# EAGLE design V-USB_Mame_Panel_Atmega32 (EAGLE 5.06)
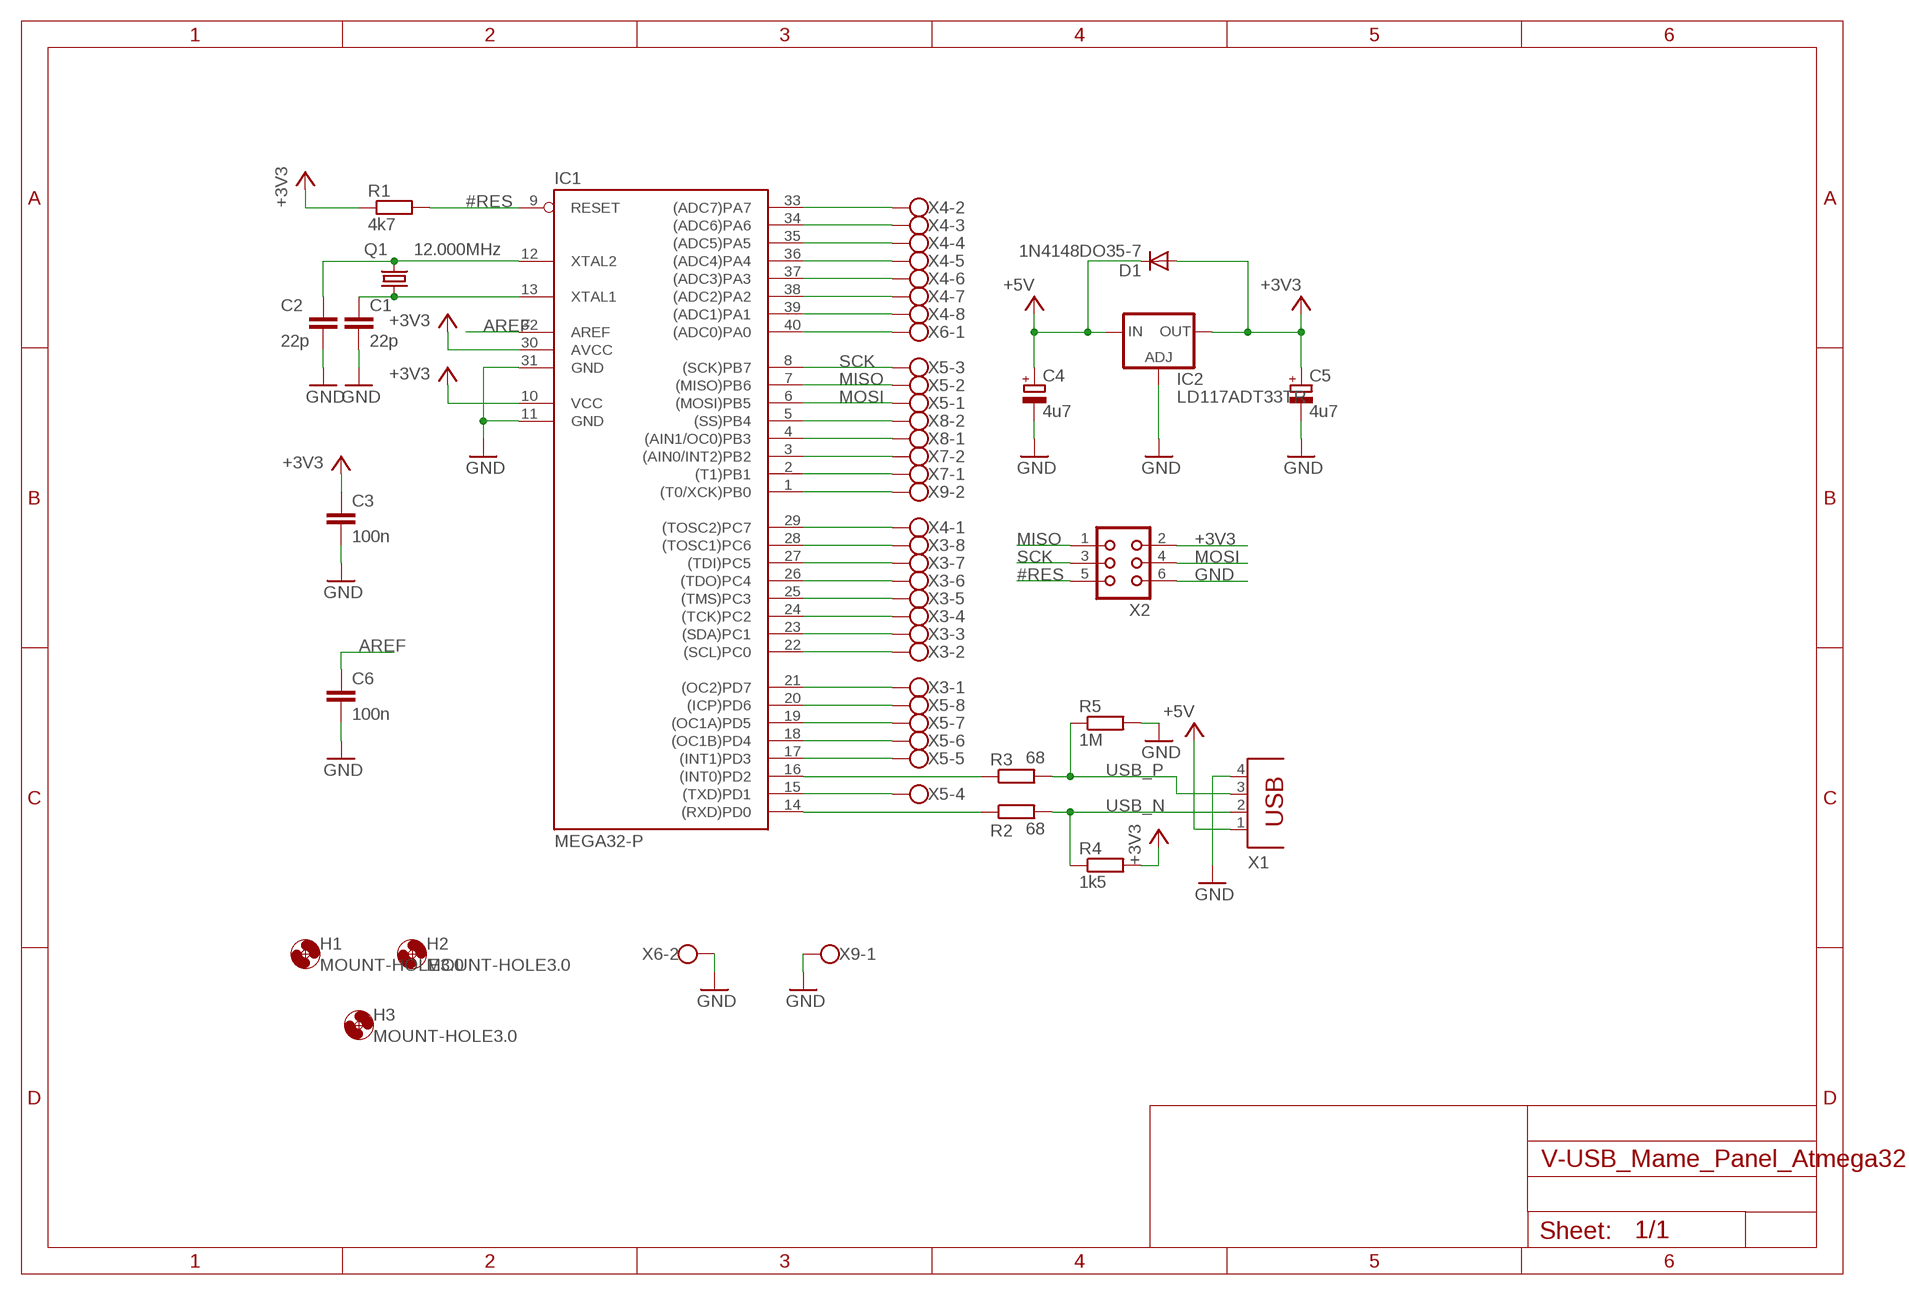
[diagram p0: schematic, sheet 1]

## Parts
C1  22p  C2.5/2  [C2.5-2]
C2  22p  C2.5/2  [C2.5-2]
C3  100n  C5/2.5  [C5B2.5]
C4  4u7  CPOL-EUE2.5-6  [E2,5-6]
C5  4u7  CPOL-EUE2.5-6  [E2,5-6]
C6  100n  C5/2.5  [C5B2.5]
D1  1N4148DO35-7  [DO35-7]
H1  MOUNT-HOLE3.0  [3,0]
H2  MOUNT-HOLE3.0  [3,0]
H3  MOUNT-HOLE3.0  [3,0]
IC1  MEGA32-P  [DIL40]
IC2  LD117ADT33TR  [DPACK]
Q1  12.000MHz  CRYSTALHC18U-V  [HC18U-V]
R1  4k7  R-EU_0207/10  [0207/10]
R2  68  R-EU_0207/10  [0207/10]
R3  68  R-EU_0207/10  [0207/10]
R4  1k5  R-EU_0207/10  [0207/10]
R5  1M  R-EU_0207/10  [0207/10]
X1  PN61729  [PN61729]
X2  CON06L  [CON06L]
X3  W237-08P  [W237-8P]
X4  W237-08P  [W237-8P]
X5  W237-08P  [W237-8P]
X6  W237-02P  [W237-132]
X7  W237-02P  [W237-132]
X8  W237-02P  [W237-132]
X9  W237-02P  [W237-132]

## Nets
#RES: IC1.9(RESET) R1.2 X2.5
+3V3: C3.1 C5.+ D1.A IC1.10(VCC) IC1.30(AVCC) IC2.4(OUT) R1.1 R4.2 X2.2
+5V: C4.+ D1.C IC2.3(IN) X1.1
AREF: C6.1 IC1.32(AREF)
GND: C1.2 C2.2 C3.2 C4.- C5.- C6.2 IC1.11(GND) IC1.31(GND) IC2.1(ADJ) R5.2 X1.4 X2.6 X6.2 X9.1
MISO: IC1.7((MISO)PB6) X2.1 X5.2
MOSI: IC1.6((MOSI)PB5) X2.4 X5.1
N$1: IC1.17((INT1)PD3) X5.5
N$2: IC1.16((INT0)PD2) R3.1
N$3: C1.1 IC1.13(XTAL1) Q1.1
N$4: C2.1 IC1.12(XTAL2) Q1.2
N$5: IC1.14((RXD)PD0) R2.1
N$6: IC1.21((OC2)PD7) X3.1
N$7: IC1.22((SCL)PC0) X3.2
N$9: IC1.2((T1)PB1) X7.1
N$10: IC1.3((AIN0/INT2)PB2) X7.2
N$11: IC1.5((SS)PB4) X8.2
N$12: IC1.4((AIN1/OC0)PB3) X8.1
N$13: IC1.15((TXD)PD1) X5.4
N$14: IC1.18((OC1B)PD4) X5.6
N$15: IC1.19((OC1A)PD5) X5.7
N$16: IC1.20((ICP)PD6) X5.8
N$17: IC1.23((SDA)PC1) X3.3
N$18: IC1.24((TCK)PC2) X3.4
N$19: IC1.25((TMS)PC3) X3.5
N$20: IC1.26((TDO)PC4) X3.6
N$21: IC1.27((TDI)PC5) X3.7
N$22: IC1.28((TOSC1)PC6) X3.8
N$23: IC1.29((TOSC2)PC7) X4.1
N$24: IC1.33((ADC7)PA7) X4.2
N$25: IC1.34((ADC6)PA6) X4.3
N$26: IC1.35((ADC5)PA5) X4.4
N$27: IC1.36((ADC4)PA4) X4.5
N$28: IC1.37((ADC3)PA3) X4.6
N$29: IC1.38((ADC2)PA2) X4.7
N$30: IC1.39((ADC1)PA1) X4.8
N$31: IC1.40((ADC0)PA0) X6.1
N$32: IC1.1((T0/XCK)PB0) X9.2
SCK: IC1.8((SCK)PB7) X2.3 X5.3
USB_N: R2.2 R4.1 X1.2
USB_P: R3.2 R5.1 X1.3

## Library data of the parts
C1-C3 C6 = capacitor-wima:C: CAPACITOR
C4 C5 = resistor:CPOL-EU: POLARIZED CAPACITOR, European symbol
D1 = diode:1N4148: DIODE
H1-H3 = holes:MOUNT-HOLE: MOUNTING HOLE with drill center marker
IC1 = atmel:MEGA32-P: MICROCONTROLLER 32 Kbytes FLASH 2 Kbytes SRAM 1 Kbytes EEPROM USART 8-channel 10 bit ADC Source: www.atmel.com .. doc2503.pdf
IC2 = v-reg:LD117A?*: Low drop fixed and adjustable positive voltage regulators 1 A Source: http://www.st.com/stonline/products/literature/ds/7194/ld1117axx.pdf
Q1 = crystal:CRYSTAL: CRYSTAL
R1-R5 = resistor:R-EU_: RESISTOR, European symbol
X1 = con-berg:PN61729: BERG USB connector
X2 = con-harting:CON06L: CONNECTOR
X3-X5 = con-wago-508:W237-08P: WAGO SREW CLAMP
X6-X9 = con-wago-508:W237-02P: WAGO SREW CLAMP

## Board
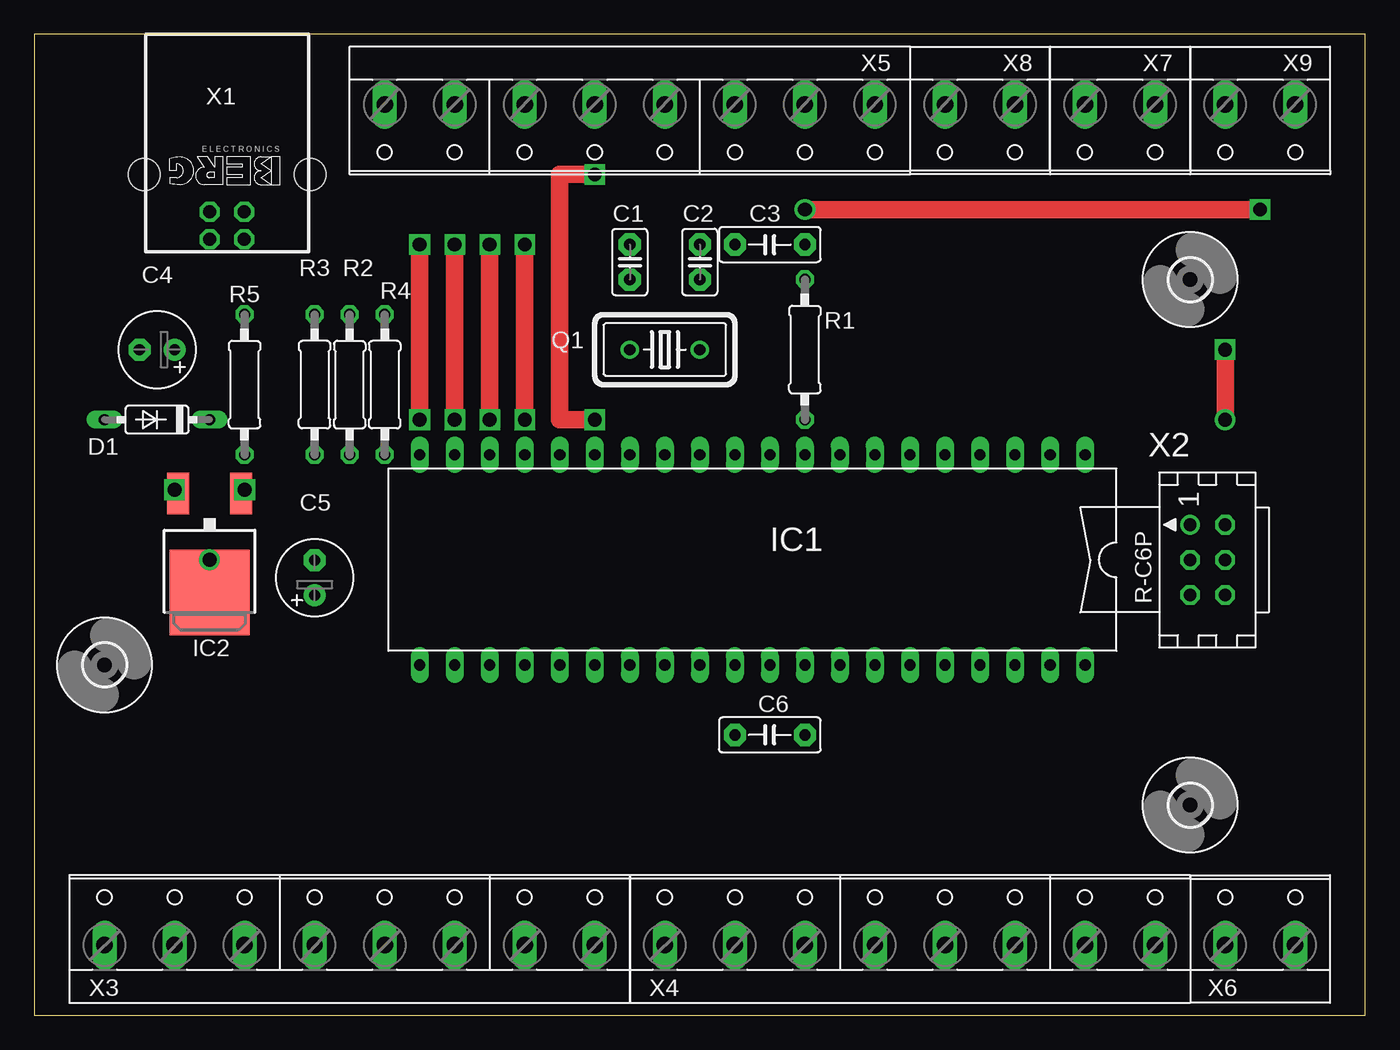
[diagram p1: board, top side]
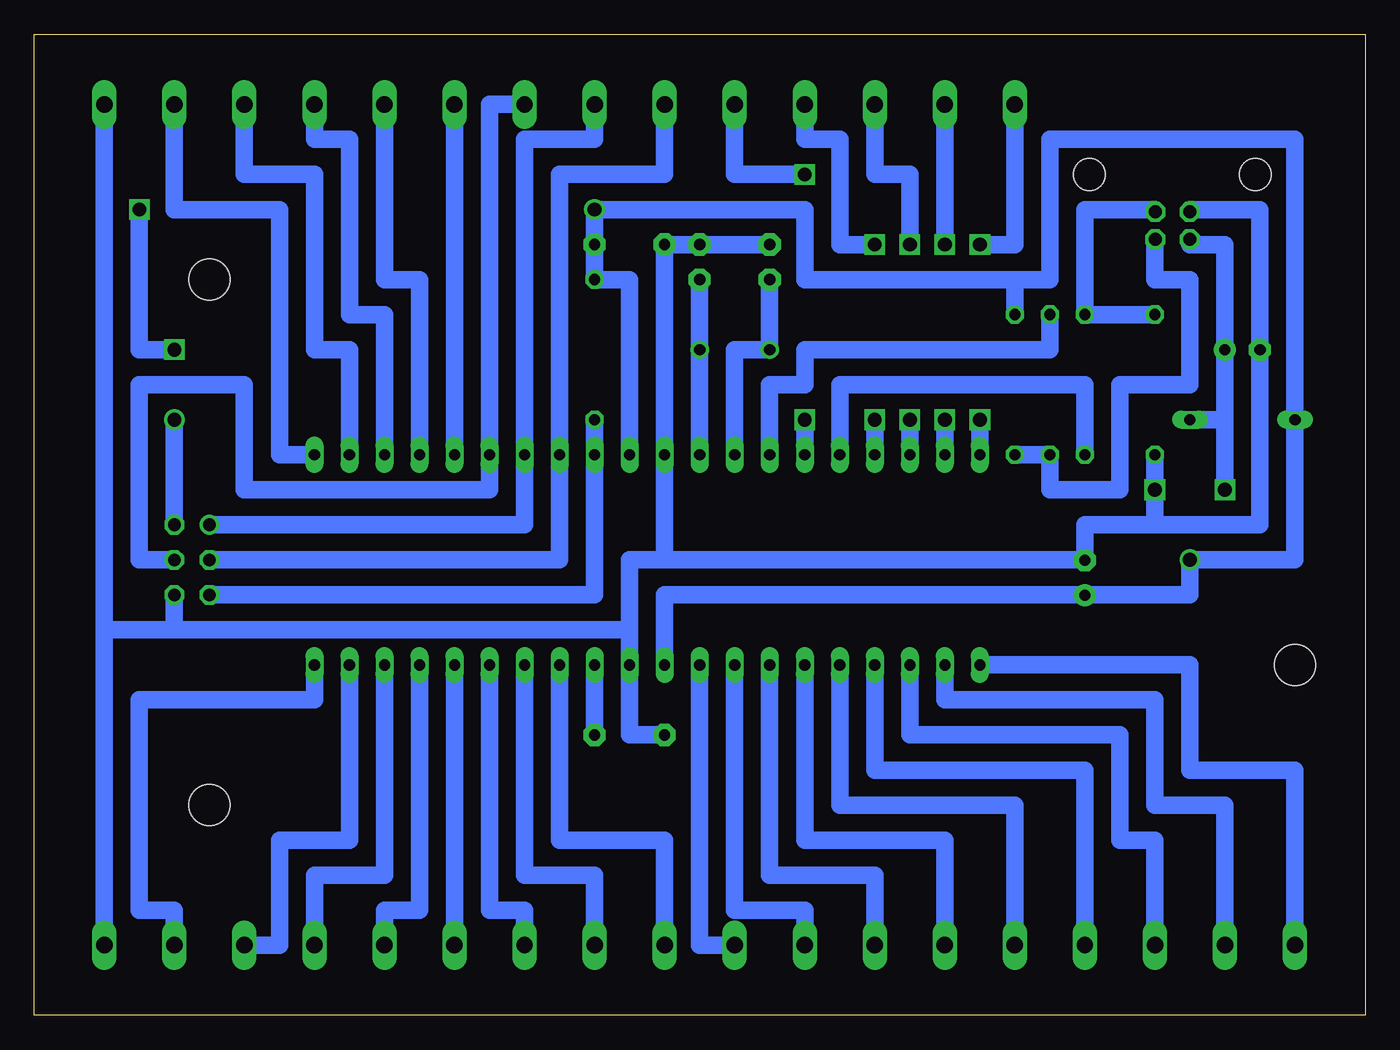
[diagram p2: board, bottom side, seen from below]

Size 96.51 x 71.11 mm. Coordinates in mm from the lower left corner, seen from the top.
Outline: 0,0 96.51,0 96.51,71.11 0,71.11 0,0
Copper layers (1*16): Top 0.035mm / dielectric 1.5mm / Bottom 0.035mm
Design rules "default": minimum track width 10mil, minimum drill 24mil, track to track 8mil, track to pad 8mil, pad to pad 8mil, via to via 8mil, smd to smd 8mil, copper to edge 40mil, drill to drill 8mil, minimum pad ring 10mil, minimum via ring 8mil, stop-mask expansion 4mil, vias tented up to drill 0mil, thermal gap 10mil

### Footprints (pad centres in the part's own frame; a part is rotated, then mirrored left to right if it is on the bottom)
C2.5-2 = drill 0.813 pad 1.6 octagon: 1 -1.27,0; 2 1.27,0
C5B2.5 = drill 0.813 pad 1.6 octagon: 1 -2.54,0; 2 2.54,0
E2,5-6 = drill 0.813 pad 1.6 round: + -1.27,0 | drill 0.813 pad 1.6 octagon: - 1.27,0
DO35-7 = drill 0.813 long: A 3.81,0; C -3.81,0
3,0 = hole 3: 0,0
DIL40 = drill 0.813 long: 1 -24.13,-7.62; 2 -21.59,-7.62; 3 -19.05,-7.62; 4 -16.51,-7.62; 5 -13.97,-7.62; 6 -11.43,-7.62; 7 -8.89,-7.62; 8 -6.35,-7.62; 9 -3.81,-7.62; 10 -1.27,-7.62; 11 1.27,-7.62; 12 3.81,-7.62; 13 6.35,-7.62; 14 8.89,-7.62; 15 11.43,-7.62; 16 13.97,-7.62; 17 16.51,-7.62; 18 19.05,-7.62; 19 21.59,-7.62; 20 24.13,-7.62; 21 24.13,7.62; 22 21.59,7.62; 23 19.05,7.62; 24 16.51,7.62; 25 13.97,7.62; 26 11.43,7.62; 27 8.89,7.62; 28 6.35,7.62; 29 3.81,7.62; 30 1.27,7.62; 31 -1.27,7.62; 32 -3.81,7.62; 33 -6.35,7.62; 34 -8.89,7.62; 35 -11.43,7.62; 36 -13.97,7.62; 37 -16.51,7.62; 38 -19.05,7.62; 39 -21.59,7.62; 40 -24.13,7.62
DPACK = smd 1.6 x 3: 1 -2.28,-4.8; 3 2.28,-4.8 | smd 5.8 x 6.2: 4 0,2.38
HC18U-V = drill 0.813 round: 1 -2.54,0; 2 2.54,0
0207/10 = drill 0.813 octagon: 1 -5.08,0; 2 5.08,0
PN61729 = drill 0.95 octagon: 1 1.25,4.71; 2 -1.25,4.71; 3 -1.25,2.71; 4 1.25,2.71 | hole 2.3: -6.02,0; 6.02,0
CON06L = drill 0.914 round: 1 2.54,1.27 | drill 0.914 octagon: 2 2.54,-1.27; 3 0,1.27; 4 0,-1.27; 5 -2.54,1.27; 6 -2.54,-1.27
W237-8P = drill 1.194 long: 1 -17.78,-0.635; 2 -12.7,-0.635; 3 -7.62,-0.635; 4 -2.54,-0.635; 5 2.54,-0.635; 6 7.62,-0.635; 7 12.7,-0.635; 8 17.78,-0.635
W237-132 = drill 1.194 long: 1 -2.54,-0.635; 2 2.54,-0.635

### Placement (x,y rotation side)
C1  43.18,54.61 90 top
C2  48.26,54.61 90 top
C3  53.34,55.88 180 top
C4  8.89,48.26 180 top
C5  20.32,31.72 90 top
C6  53.34,20.32 180 top
D1  8.89,43.18 180 top
H1  83.82,53.34 0 top
H2  83.82,15.24 0 top
H3  5.08,25.4 0 top
IC1  52.07,33.02 180 top
IC2  12.7,33.02 180 top
Q1  45.72,48.26 0 top
R1  55.88,48.26 270 top
R2  22.86,45.72 270 top
R3  20.32,45.72 90 top
R4  25.4,45.72 90 top
R5  15.24,45.72 270 top
X1  13.97,60.96 180 top
X2  85.09,33.02 90 top
X3  22.86,5.71 0 top
X4  63.5,5.71 0 top
X5  43.18,65.41 180 top
X6  88.9,5.71 0 top
X7  78.74,65.41 180 top
X8  68.58,65.41 180 top
X9  88.9,65.41 180 top

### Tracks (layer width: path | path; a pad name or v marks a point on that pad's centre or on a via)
#RES
  Bottom 1.27: X2.5 55.88,30.48 IC1.9 R1.2
+3V3  (via drill 1)
  Top 1.27: v86.36,48.26 v86.36,43.18 | v55.88,58.42 v88.9,58.42 | v12.7,33.02 IC2.4
  Bottom 1.27: IC1.30 50.8,30.48 17.78,30.48 | C3.1 v55.88,58.42 40.64,58.42 40.64,53.34 25.4,53.34 | C3.1 R1.1 | v86.36,43.18 X2.2 | IC1.10 53.34,53.34 R1.1 | 17.78,30.48 C5.+ | 17.78,30.48 12.7,30.48 IC2.4 v12.7,33.02 5.08,33.02 D1.A 5.08,63.5 22.86,63.5 22.86,53.34 25.4,53.34 | C3.1 R1.1 | 25.4,53.34 R4.2 | v88.9,58.42 88.9,48.26 v86.36,48.26
+5V  (via drill 1)
  Top 1.27: IC2.3 10.16,37.82 v10.16,38.1
  Bottom 1.27: X1.1 12.7,56.25 12.7,55.88 10.16,55.88 C4.+ 10.16,43.18 | 10.16,43.18 D1.C | v10.16,38.1 10.16,43.18
AREF
  Bottom 1.27: C6.1 IC1.32
GND  (via drill 1)
  Top 1.27: v15.24,38.1 14.98,38.1 IC2.1
  Bottom 0.406: C2.2 C1.2 C2.2
  Bottom 1.27: C1.2 C2.2 C3.2 IC1.11 50.8,33.02 | 50.8,33.02 20.32,33.02 C5.- 20.32,35.56 15.24,35.56 | 53.34,27.94 IC1.31 53.34,20.32 C6.2 | 86.36,27.94 X2.6 | 53.34,27.94 86.36,27.94 | 86.36,27.94 91.44,27.94 | 91.44,27.94 X6.2 | 91.44,27.94 X9.1 | X1.4 12.7,58.25 12.7,58.42 7.62,58.42 C4.- 7.62,35.56 15.24,35.56 | 15.24,35.56 v15.24,38.1 R5.2 | 50.8,33.02 53.34,33.02 53.34,27.94
MISO
  Bottom 1.27: X2.1 60.96,35.56 IC1.7 60.96,63.5 55.88,63.5 X5.2
MOSI
  Bottom 1.27: X2.4 88.9,33.02 88.9,45.72 81.28,45.72 81.28,38.1 63.5,38.1 IC1.6 63.5,66.04 X5.1
N$1  (via drill 1)
  Top 1.27: v35.56,43.18 v35.56,55.88
  Bottom 1.27: IC1.17 v35.56,43.18 | v35.56,55.88 38.1,55.88 38.1,63.5 40.64,63.5 X5.5
N$2
  Bottom 1.27: IC1.16 38.1,45.72 20.32,45.72 R3.1
N$3
  Bottom 0.406: Q1.1 C1.1
  Bottom 1.27: C1.1 Q1.1 45.72,48.26 IC1.13
N$4
  Bottom 0.406: Q1.2 C2.1
  Bottom 1.27: C2.1 Q1.2 IC1.12
N$5
  Bottom 1.27: IC1.14 43.18,45.72 40.64,45.72 40.64,48.26 22.86,48.26 R2.1
N$6
  Bottom 1.27: IC1.21 12.7,25.4 12.7,17.78 5.08,17.78 X3.1
N$7
  Bottom 1.27: IC1.22 30.48,22.86 15.24,22.86 15.24,15.24 10.16,15.24 X3.2
N$9
  Bottom 1.27: X7.1 81.28,60.96 76.2,60.96 76.2,48.26 73.66,48.26 IC1.2
N$10
  Bottom 1.27: IC1.3 71.12,50.8 73.66,50.8 73.66,63.5 76.2,63.5 X7.2
N$11
  Bottom 1.27: IC1.5 X8.2
N$12
  Bottom 1.27: IC1.4 68.58,53.34 71.12,53.34 X8.1
N$13  (via drill 1)
  Top 1.27: v40.64,60.96 38.1,60.96 38.1,43.18 v40.64,43.18
  Bottom 1.27: IC1.15 v40.64,43.18 | v40.64,60.96 45.72,60.96 X5.4
N$14  (via drill 1)
  Top 1.27: v33.02,43.18 v33.02,55.88
  Bottom 1.27: IC1.18 v33.02,43.18 | v33.02,55.88 33.02,60.96 35.56,60.96 X5.6
N$15  (via drill 1)
  Top 1.27: v30.48,43.18 v30.48,55.88
  Bottom 1.27: IC1.19 v30.48,43.18 | v30.48,55.88 X5.7
N$16  (via drill 1)
  Top 1.27: v27.94,43.18 v27.94,55.88
  Bottom 1.27: IC1.20 v27.94,43.18 | X5.8 25.4,55.88 v27.94,55.88
N$17
  Bottom 1.27: IC1.23 33.02,20.32 17.78,20.32 17.78,12.7 15.24,12.7 X3.3
N$18
  Bottom 1.27: IC1.24 35.56,17.78 20.32,17.78 X3.4
N$19
  Bottom 1.27: IC1.25 38.1,15.24 25.4,15.24 X3.5
N$20
  Bottom 1.27: IC1.26 40.64,12.7 30.48,12.7 X3.6
N$21
  Bottom 1.27: IC1.27 43.18,10.16 35.56,10.16 X3.7
N$22
  Bottom 1.27: IC1.28 45.72,7.62 40.64,7.62 X3.8
N$23
  Bottom 1.27: IC1.29 48.26,5.08 X4.1
N$24
  Bottom 1.27: IC1.33 58.42,12.7 50.8,12.7 X4.2
N$25
  Bottom 1.27: IC1.34 60.96,10.16 55.88,10.16 X4.3
N$26
  Bottom 1.27: IC1.35 63.5,7.62 60.96,7.62 X4.4
N$27
  Bottom 1.27: X4.5 IC1.36
N$28
  Bottom 1.27: IC1.37 68.58,7.62 71.12,7.62 X4.6
N$29
  Bottom 1.27: IC1.38 71.12,10.16 76.2,10.16 X4.7
N$30
  Bottom 1.27: IC1.39 73.66,12.7 78.74,12.7 78.74,5.08 X4.8
N$31
  Bottom 1.27: X6.1 86.36,7.62 88.9,7.62 88.9,22.86 76.2,22.86 IC1.40
N$32
  Bottom 1.27: X9.2 86.36,58.42 78.74,58.42 78.74,40.64 IC1.1
SCK
  Bottom 1.27: X2.3 58.42,33.02 IC1.8 58.42,60.96 50.8,60.96 X5.3
USB_N
  Bottom 1.27: X1.2 15.24,56.25 15.24,53.34 12.7,53.34 12.7,45.72 17.78,45.72 17.78,38.1 22.86,38.1 R2.2 R4.1
USB_P
  Bottom 1.27: X1.3 15.24,58.25 15.24,58.42 20.32,58.42 R3.2 R5.1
